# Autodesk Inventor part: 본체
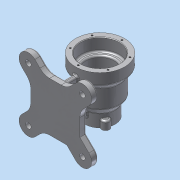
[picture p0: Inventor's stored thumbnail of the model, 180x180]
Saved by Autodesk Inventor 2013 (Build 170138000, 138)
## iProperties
Created: 2017-03
Part Number: 본체
Material: 알루미늄 6061
Document SubType Name: Modeling
Designer: dgall
Density: 2.71 g/cm^3
Mass: 1007.16 g
Surface Area: 841.793 cm^2
Volume: 371.647 cm^3
Author: dgall
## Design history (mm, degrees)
sketch "스케치2"
  geometry: L1 (45, 50)-(45, 30); L2 (45, 30)-(36, 19); L3 (36, 19)-(36, -15); L4 (36, -15)-(27.5, -27); L5 (27.5, -27)-(27.5, -50); L6 (27.5, -50)-(0, -50); L7 (0, -50)-(0, 50); L8 (0, 50)-(45, 50); 2 further points
  constraints: 16 end point, 2 coincident, 2 parallel, 2 perpendicular, 1 midpoint, 1 vertical
  dimensions: "d6" = 20 distance of L1.start L1.end; "d8" = 31 vertical distance of L1.start L2.end; "d9" = 65 vertical distance of L1.start L3.end; "d10" = 23 distance of L4.end L5.end; "d11" = 100 vertical distance of L1.start L5.end; "d12" = 90 diameter of L1 L7; "d13" = 72 diameter of L3 L7; "d14" = 55 diameter of L5 L7
revolve "회전1" sketch "스케치2" stored, may be unused: angle "d15" = 90 deg
sketch "스케치3"
  geometry: C1 r 5 at (0, 0); 1 further point
  constraints: 1 centre point, 1 coincident
  dimensions: "d16" = 10 diameter of C1
extrude "돌출1" join sketch "스케치3" distance "d17" = 40; taper "d18" = 0 deg
node "작업 평면1"
sketch "스케치4"
  geometry: L1 (-45, 45)-(45, 45); L2 (45, 45)-(45, -45); L3 (45, -45)-(-45, -45); L4 (-45, -45)-(-45, 45); L5 (-37.477, 61.518)-(-20.958, 45); L6 (-61.518, 37.477)-(-45, 20.958); L7 (37.477, 61.518)-(20.958, 45); L8 (61.518, 37.477)-(45, 20.958); L9 (37.477, -61.518)-(20.958, -45); L10 (45, -20.958)-(61.518, -37.477); L11 (-61.518, -37.477)-(-45, -20.958); L12 (-20.958, -45)-(-37.477, -61.518); A1 r 70 centre (0, 0) between (-49.497, 49.497) and (-59.97, -36.106); A2 r 17 centre (-49.497, 49.497) between (-37.477, 61.518) and (-61.518, 37.477); A3 r 17 centre (-49.497, -49.497) between (-61.518, -37.477) and (-37.477, -61.518); A4 r 17 centre (49.497, -49.497) between (37.477, -61.518) and (61.518, -37.477); A5 r 17 centre (49.497, 49.497) between (61.518, 37.477) and (37.477, 61.518); 3 further points
  constraints: 24 end point, 13 point on circle, 8 point on line, 7 tangent, 5 centre point, 4 equal length, 3 parallel, 3 perpendicular, 2 midpoint, 1 coincident, 1 horizontal, 1 horizontal alignment, 1 vertical alignment, 17 other
  dimensions: "d20" = 90 distance of L1.start L1.end; "d22" = 140 diameter of A1; "d25" = 45 deg dimension on point (0, 0) point (-45, 0) A1.start; "d28" = 360 deg dimension on point (0, 0) A1.start (derived); "d114" = 34 diameter of A2
extrude "돌출2" join sketch "스케치4" distance "d30" = 12; taper "d31" = 0 deg
fillet "모깎기1" dims "d32" = 25
sketch "스케치5"
  geometry: L1 (-4, -37)-(4, -37); L2 (4, -37)-(4, 37); L3 (4, 37)-(-4, 37); L4 (-4, 37)-(-4, -37); 3 further points
  constraints: 8 end point, 2 midpoint, 2 parallel, 1 horizontal, 1 horizontal alignment, 1 perpendicular, 1 vertical alignment
  dimensions: "d36" = 74 distance of L3.end L1.start; "d38" = 8 distance of L2.end L3.end
extrude "돌출3" join sketch "스케치5" stored distance "d39" = 0; taper "d40" = 0 deg
sketch "스케치6"
  geometry: L1 (-28.281, -70)-(-37.477, -70) reference; L2 (-10.603, -70)-(-28.281, -70) reference; L3 (-25, -70)-(-18.14, -31.096); L4 (18.14, -31.096)-(25, -70); L5 (37.477, -70)-(20.958, -70) reference; L6 (20.958, -70)-(-10.603, -70) reference; A1 r 36 centre (0, 0) between (4, -35.777) and (-4, -35.777) reference; 1 further point
  constraints: 4 end point, 2 point on circle, 2 point on line, 1 horizontal alignment
  dimensions: "d41" = 25 horizontal distance of L3.start point (0, 0); "d42" = 25 horizontal distance of L4.end point (0, 0); "d43" = 100 deg angle of L1 L3
extrude "돌출4" join sketch "스케치6" stored distance "d44" = 8; taper "d45" = 0 deg
sketch "스케치7"
  geometry: C1 r 45 at (0, 0) reference; C2 r 35 at (0, 0)
  constraints: 1 centre point, 1 coincident
  dimensions: "d46" = 70 diameter of C2
extrude "돌출5" cut sketch "스케치7" distance "d47" = 23; taper "d48" = 0 deg
sketch "스케치8"
  geometry: C1 r 35 at (0, 0) reference; C2 r 26 at (0, 0)
  constraints: 1 centre point, 1 coincident
  dimensions: "d49" = 52 diameter of C2
extrude "돌출6" cut sketch "스케치8" distance "d50" = 47; taper "d51" = 0 deg
sketch "스케치9"
  geometry: C1 r 26 at (0, 0) reference; C2 r 17.5 at (0, 0)
  constraints: 1 centre point, 1 coincident
  dimensions: "d52" = 35 diameter of C2
extrude "돌출7" cut sketch "스케치9" distance "d54" = 30; taper "d55" = 0 deg
hole "구멍1" diameter "d58" = 4.134; stored, may be unused: countersink angle "d62" = 90 deg, drill point angle "d64" = 118 deg; dims "d59" = 100, "d60" = 4, "d61" = 2, "d63" = 8, "d65" = 10, "d66" = 10
sketch "스케치10"
  geometry: C1 r 17.5 at (0, 0) reference; C2 r 7 at (0, 27.5); C3 r 7 at (-23.816, -13.75); C4 r 7 at (23.816, -13.75); 1 further point
  constraints: 3 centre point, 2 vertical alignment, 8 other
  dimensions: "d67" = 14 diameter of C2; "d71" = 360 deg dimension on C1.centre C2.centre (derived)
extrude "돌출8" join sketch "스케치10" distance "d73" = 15; taper "d74" = 0 deg
sketch "스케치11"
  geometry: A1 r 7 centre (0, 0) between (6.943, -0.891) and (-6.943, -0.891) reference; A2 r 7 centre (-23.816, -41.25) between (-26.516, -34.792) and (-19.573, -46.817) reference; A3 r 7 centre (23.816, -41.25) between (19.573, -46.817) and (26.516, -34.792) reference; 3 further points
  constraints: 3 coincident
hole "구멍2" sketch "스케치11" at (-23.816, -41.25), (23.816, -41.25), (0, 0) diameter "d75" = 3.242; stored, may be unused: countersink angle "d79" = 90 deg, drill point angle "d81" = 118 deg; dims "d76" = 9, "d77" = 4, "d78" = 2, "d80" = 11
sketch "스케치12"
  geometry: C1 r 35 at (0, 0) reference; 1 further point
  constraints: 1 vertical alignment
  dimensions: "d82" = 40 distance of C1.centre point (0, 40)
hole "구멍3" sketch "스케치12" at (0, 40) diameter "d83" = 3.242; stored, may be unused: countersink angle "d87" = 90 deg, drill point angle "d89" = 118 deg; dims "d84" = 9, "d85" = 4, "d86" = 2, "d88" = 11
sketch "스케치13"
  geometry: L1 (20.958, 45)-(-10.603, 45) reference; 3 further points
  constraints: 1 other
  dimensions: "d93" = 35 distance of point (35, 0) point (0, 0); "d94" = 45 distance from line of point (35, 0) L1
feature "엠보싱1" sketch "스케치13" dims "d6" = 20, "d8" = 31, "d9" = 65, "d10" = 23, "d11" = 100, "d12" = 90, "d13" = 72, "d14" = 55, "d20" = 90, "d22" = 140, "d25" = 45 deg, "d28" = 360 deg (derived), "d95" = 0.5, "d96" = 0, "d114" = 34
fillet "모깎기2" dims "d97" = 3
sketch "스케치14"
  geometry: A1 r 14 centre (-49.497, 49.497) between (-39.598, 59.397) and (-59.397, 39.598) reference; A2 r 14 centre (-49.497, -49.497) between (-59.397, -39.598) and (-39.598, -59.397) reference; A3 r 14 centre (49.497, -49.497) between (39.598, -59.397) and (59.397, -39.598) reference; A4 r 14 centre (49.497, 49.497) between (59.397, 39.598) and (39.598, 59.397) reference; 8 further points
  constraints: 4 coincident
hole "구멍4" sketch "스케치14" at (-49.497, -49.497), (-49.497, 49.497), (49.497, 49.497), (49.497, -49.497) diameter "d98" = 10; stored, may be unused: countersink angle "d102" = 90 deg, drill point angle "d104" = 118 deg; dims "d99" = 9, "d100" = 4, "d101" = 2, "d103" = 11
fillet "모깎기3" dims "d105" = 3
fillet "모깎기4" dims "d106" = 3
fillet "모깎기5" dims "d107" = 3
fillet "모깎기6" dims "d108" = 1
chamfer "모따기1" distance "d109" = 1; stored, may be unused: second distance "d110" = 2, angle "d111" = 45 deg
fillet "모깎기7" dims "d112" = 3
node "솔리드1"
pattern_circular "원형 패턴1" dims angle "d91" = 360 deg
other parameters: "d19" = -82
